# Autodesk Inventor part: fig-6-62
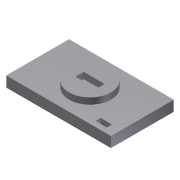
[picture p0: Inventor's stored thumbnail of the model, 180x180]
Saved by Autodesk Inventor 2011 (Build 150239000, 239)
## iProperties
Created: 2007-01
Part Number: fig-6-62
Document SubType Name: Modeling
Designer: Administrator
Density: 1 g/cm^3
Author: Administrator
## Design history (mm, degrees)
sketch "Sketch1"
  geometry: L1 (-50, 30)-(50, 30); L2 (50, 30)-(50, -30); L3 (50, -30)-(-50, -30); L4 (-50, -30)-(-50, 30); 1 further point
  constraints: 8 end point, 2 parallel, 1 horizontal, 1 perpendicular, 1 other
  dimensions: "d0" = 50 distance from line of L4 point (0, 0); "d1" = 100 distance of L1.start L1.end; "d2" = 30 distance from line of L3 point (0, 0); "d3" = 60 distance between parallel lines of L3 L1
extrude "Extrusion1" new body sketch "Sketch1" distance "d4" = 10; taper "d5" = 0 deg
sketch "Sketch2"
  geometry: L1 (10, -4)-(-10, -4); L2 (-10, -4)-(-10, 4); L3 (-10, 4)-(10, 4); L4 (10, 4)-(10, -4); C1 r 20 at (0, 0); 1 further point
  constraints: 8 end point, 2 parallel, 1 centre point, 1 coincident, 1 horizontal, 1 perpendicular, 1 other
  dimensions: "d6" = 40 diameter of C1; "d7" = 4 distance from line of L3 point (0, 0); "d8" = 8 distance between parallel lines of L1 L3; "d9" = 10 distance from line of L2 point (0, 0); "d10" = 20 distance between parallel lines of L4 L2
extrude "Extrusion2" join sketch "Sketch2" distance "d11" = 6; taper "d12" = 0 deg
sketch "Sketch3"
  geometry: L1 (30, -20)-(41, -20); L2 (41, -20)-(41, -25); L3 (41, -25)-(30, -25); L4 (30, -25)-(30, -20)
  constraints: 8 end point, 2 parallel, 1 horizontal, 1 perpendicular
extrude "Extrusion3" cut sketch "Sketch3" stored distance "d13" = 10; taper "d14" = 0 deg
body "Solid1"
